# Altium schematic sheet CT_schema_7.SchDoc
size 287 x 160 mm
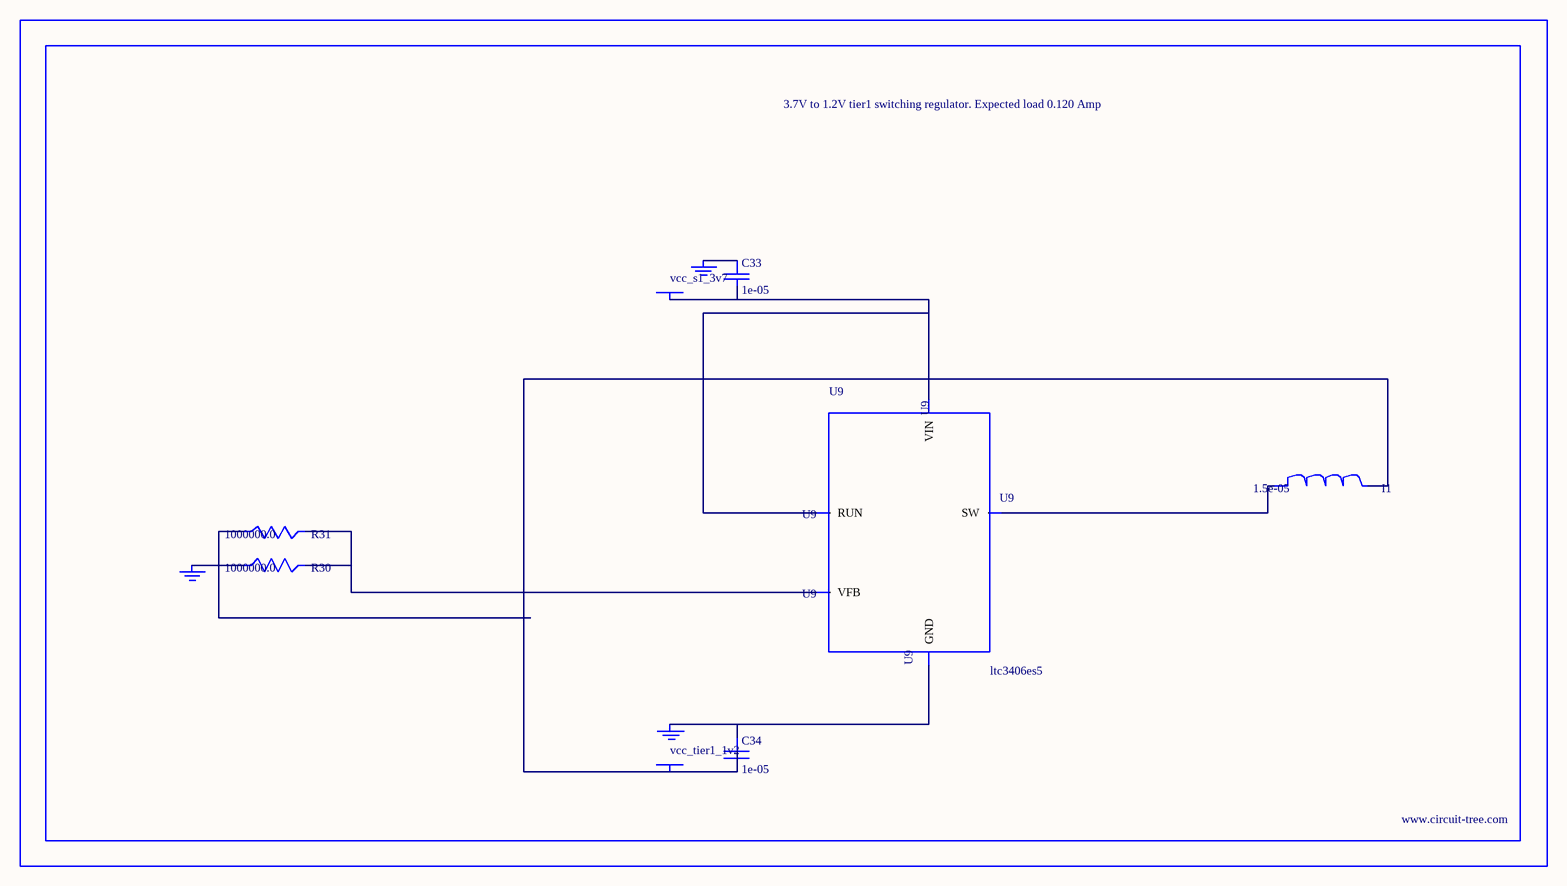
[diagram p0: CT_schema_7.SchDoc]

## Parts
BORDER6  (no value)
C33  1e-05  [C0805]
C34  1e-05  [C0805]
GND_INSTANCE_6_0  (no value)
GND_INSTANCE_6_1  (no value)
GND_INSTANCE_6_2  (no value)
I1  1.5e-05  [L1210]
POWER_INSTANCE_6_0  vcc_tier1_1v2
POWER_INSTANCE_6_1  vcc_s1_3v7
R30  1000000.0  [R0603]
R31  1000000.0  [R0603]
U9  ltc3406es5  [TSOT-23-5]

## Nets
NetC33_1: C33.1 GND_INSTANCE_6_1.0(GND)
NetC33_2: C33.2 POWER_INSTANCE_6_1.0(PWR) U9.1(RUN) U9.4(VIN)
NetC34_1: C34.1 GND_INSTANCE_6_0.0(GND) U9.2(GND)
NetC34_2: C34.2 I1.2 POWER_INSTANCE_6_0.0(PWR) R31.1
NetGND_INSTANCE_6_2_0: GND_INSTANCE_6_2.0(GND) R30.1
NetI1_1: I1.1 U9.3(SW)
NetR30_2: R30.2 R31.2 U9.5(VFB)

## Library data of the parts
BORDER6 = BORDER_PAGE6
C33 C34 = C0805C106K8RACTU
GND_INSTANCE_6_0-GND_INSTANCE_6_2 = GND
I1 = L1210R150MDWIT
POWER_INSTANCE_6_0 POWER_INSTANCE_6_1 = PWR
R30 R31 = RC0603JR-071ML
